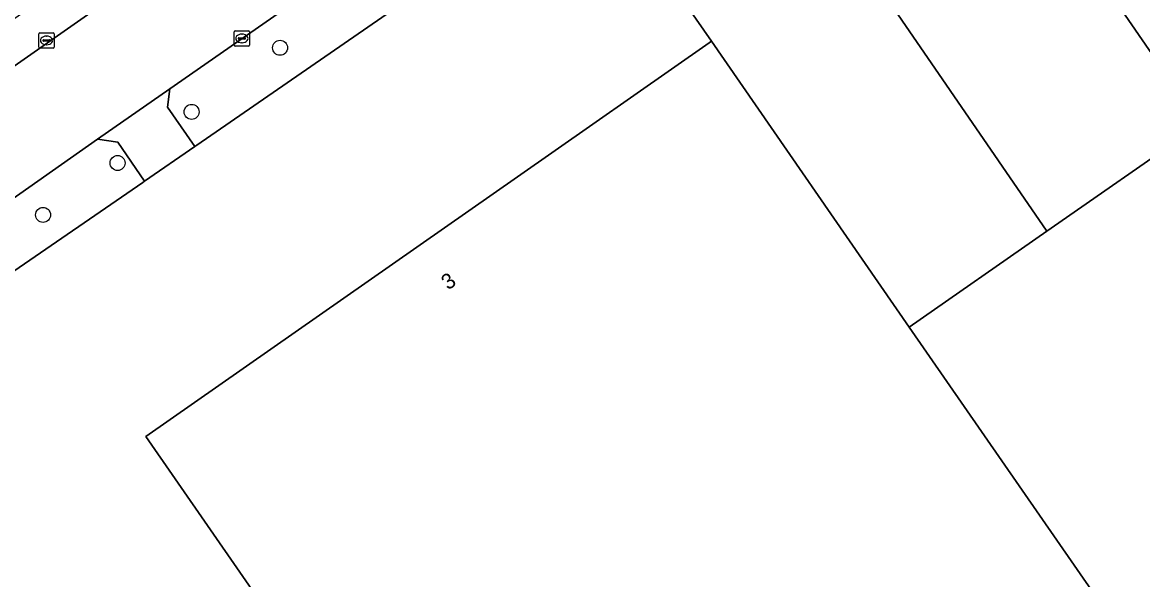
# Model space of a CAD drawing. Extents: x 156702 to 158052, y 387630 to 388992.
# Drawn here: x 157218.4 to 157291.3, y 388018.3 to 388054.6 of the extents above; entities that cross this region are included whole.
import ezdxf

# ---------------------------------------------------------------- set-up
doc = ezdxf.new("R2010")
doc.units = 0
for name, color, linetype in [('IMGEO_Berm_groen', 7, 'Continuous'), ('IMGEO_Boom', 7, 'Continuous'), ('IMGEO_Erf', 7, 'Continuous'), ('IMGEO_Kolk', 7, 'Continuous'), ('IMGEO_Pand', 7, 'Continuous'), ('IMGEO_Pand_nummerreeks', 7, 'Continuous'), ('IMGEO_Parkeervlak_open', 7, 'Continuous'), ('IMGEO_Rijbaan_lokaal_gesloten', 7, 'Continuous'), ('IMGEO_Voetpad_open', 7, 'Continuous')]:
    doc.layers.add(name, color=color, linetype=linetype)

msp = doc.modelspace()

# ---------------------------------------------------------------- linework, layer by layer
at = {"layer": 'IMGEO_Berm_groen'}
for points in [[(157243.07, 388055.771), (157240.821, 388059.195), (157228.017, 388050.255), (157227.867, 388049.069), (157229.656, 388046.52), (157229.78, 388046.605)], [(157226.257, 388044.175), (157226.369, 388044.252), (157224.647, 388046.795), (157223.322, 388046.977), (157216.483, 388042.202), (157217.546, 388040.691), (157216.399, 388039.902), (157217.532, 388038.158)]]:
    msp.add_lwpolyline(points, close=True, dxfattribs=at)
at = {"layer": 'IMGEO_Boom'}
for centre in [(157235.188, 388052.93), (157229.437, 388048.762), (157224.623, 388045.438), (157219.777, 388042.063)]:
    msp.add_circle(centre, 0.489, dxfattribs=at)
at = {"layer": 'IMGEO_Erf'}
for points in [[(157295.814, 388092.422), (157290.104, 388088.445), (157280.155, 388081.516), (157245.365, 388057.354), (157243.07, 388055.771), (157229.78, 388046.605), (157229.656, 388046.52), (157226.369, 388044.252), (157226.257, 388044.175), (157217.532, 388038.158), (157206.185, 388030.086), (157205.385, 388029.517), (157201.094, 388026.55), (157192.622, 388020.62), (157173.094, 388007.069), (157165.32, 388001.584), (157139.646, 387983.642), (157132.369, 387978.596), (157115.369, 387966.676)], [(157240.973, 388006.687), (157226.45, 388027.647), (157250.631, 388044.541), (157263.091, 388053.246), (157263.242, 388053.365), (157260.745, 388056.949)]]:
    msp.add_lwpolyline(points, dxfattribs=at)
at = {"layer": 'IMGEO_Kolk'}
for p, q in [((157219.503, 388052.979), (157219.503, 388053.831)), ((157219.578, 388053.905), (157220.43, 388053.905)), ((157219.991, 388053.685), (157220.016, 388053.685)), ((157220.504, 388053.831), (157220.504, 388052.979)), ((157232.204, 388053.109), (157232.204, 388053.961)), ((157232.279, 388054.035), (157233.131, 388054.035)), ((157232.463, 388053.529), (157232.463, 388053.541)), ((157232.901, 388053.492), (157232.503, 388053.492)), ((157232.506, 388053.578), (157232.904, 388053.578)), ((157232.692, 388053.815), (157232.717, 388053.815)), ((157232.947, 388053.541), (157232.947, 388053.529)), ((157233.205, 388053.961), (157233.205, 388053.109)), ((157220.43, 388052.905), (157219.578, 388052.905)), ((157219.762, 388053.399), (157219.762, 388053.411)), ((157220.2, 388053.362), (157219.802, 388053.362)), ((157219.805, 388053.448), (157220.203, 388053.448)), ((157220.014, 388053.125), (157219.989, 388053.125)), ((157220.246, 388053.411), (157220.246, 388053.399)), ((157233.131, 388053.035), (157232.279, 388053.035)), ((157232.715, 388053.255), (157232.69, 388053.255))]:
    msp.add_line(p, q, dxfattribs=at)
for points in [[(157219.503, 388052.979), (157219.503, 388053.831)], [(157219.578, 388053.905), (157220.43, 388053.905)], [(157220.504, 388053.831), (157220.504, 388052.979)], [(157232.204, 388053.109), (157232.204, 388053.961)], [(157232.279, 388054.035), (157233.131, 388054.035)], [(157233.205, 388053.961), (157233.205, 388053.109)], [(157220.43, 388052.905), (157219.578, 388052.905)], [(157233.131, 388053.035), (157232.279, 388053.035)]]:
    msp.add_lwpolyline(points, dxfattribs=at)
for centre, radius, start, end in [((157219.58, 388053.829), 0.0765, 91.55205, 178.44795), ((157219.58, 388053.829), 0.0765, 91.55205, 178.44795), ((157220.428, 388053.829), 0.0765, 1.55205, 88.44795), ((157220.428, 388053.829), 0.0765, 1.55205, 88.44795), ((157232.281, 388053.959), 0.0765, 91.55205, 178.44795), ((157232.281, 388053.959), 0.0765, 91.55205, 178.44795), ((157232.503, 388053.538), 0.0403, 85.87752, 175.75265), ((157232.5, 388053.528), 0.0366, 178.93798, 274.71019), ((157232.904, 388053.535), 0.043, 264.86636, 352.45326), ((157232.908, 388053.54), 0.0386, 1.73085, 96.63898), ((157233.129, 388053.959), 0.0765, 1.55205, 88.44795), ((157233.129, 388053.959), 0.0765, 1.55205, 88.44795), ((157219.58, 388052.981), 0.0765, 181.55205, 268.44795), ((157219.58, 388052.981), 0.0765, 181.55205, 268.44795), ((157219.802, 388053.408), 0.0403, 85.87752, 175.75265), ((157219.799, 388053.398), 0.0366, 178.93798, 274.71019), ((157220.203, 388053.405), 0.043, 264.86636, 352.45326), ((157220.207, 388053.41), 0.0386, 1.73085, 96.63898), ((157220.428, 388052.981), 0.0765, 271.55205, 358.44795), ((157220.428, 388052.981), 0.0765, 271.55205, 358.44795), ((157232.281, 388053.111), 0.0765, 181.55205, 268.44795), ((157232.281, 388053.111), 0.0765, 181.55205, 268.44795), ((157233.129, 388053.111), 0.0765, 271.55205, 358.44795), ((157233.129, 388053.111), 0.0765, 271.55205, 358.44795)]:
    msp.add_arc(centre, radius, start, end, dxfattribs=at)
for centre, major_axis, ratio, start_param, end_param in [((157219.99, 388053.405), (-0.387, 0.002), 0.722429, 4.712389, 7.853982), ((157220.015, 388053.405), (-0.39, 0.002), 0.717154, 1.570796, 4.712389), ((157232.691, 388053.535), (-0.387, 0.002), 0.722429, 4.712389, 7.853982), ((157232.716, 388053.535), (-0.39, 0.002), 0.717154, 1.570796, 4.712389)]:
    msp.add_ellipse(centre, major_axis=major_axis, ratio=ratio, start_param=start_param, end_param=end_param, dxfattribs=at)
at = {"layer": 'IMGEO_Pand'}
for points in [[(157304.913, 388054.921), (157289.283, 388077.665), (157285.704, 388076.799), (157285.763, 388076.496), (157286.07, 388076.547), (157287, 388075.214), (157280.679, 388070.849), (157280.518, 388071.054), (157279.321, 388070.766), (157295.004, 388048.007)], [(157285.053, 388040.999), (157294.657, 388047.688), (157295.004, 388048.007), (157279.321, 388070.766), (157275.859, 388069.933), (157275.932, 388069.637), (157276.254, 388069.681), (157277.167, 388068.366), (157270.869, 388063.99), (157270.673, 388064.204), (157269.327, 388063.886)], [(157285.053, 388040.999), (157269.327, 388063.886), (157266.032, 388063.108), (157266.111, 388062.802), (157266.373, 388062.831), (157267.312, 388061.487), (157260.745, 388056.949), (157263.242, 388053.365), (157276.098, 388034.761)], [(157333.716, 388032.919), (157325.284, 388045.037), (157326.381, 388046.439), (157323.784, 388048.53), (157323.348, 388047.818), (157319.026, 388054.029), (157308.289, 388046.541), (157309.049, 388045.451), (157300.378, 388039.443), (157294.657, 388047.688), (157285.053, 388040.999), (157276.098, 388034.761), (157297.752, 388003.524), (157297.944, 388003.658), (157299.616, 388001.233), (157322.97, 388017.506), (157327.072, 388020.364), (157323.352, 388025.662)], [(157276.098, 388034.761), (157263.242, 388053.365), (157263.091, 388053.246), (157250.631, 388044.541), (157226.45, 388027.647), (157240.973, 388006.687), (157245.602, 388000), (157260.917, 387977.877), (157292.934, 388000), (157292.855, 388000.114), (157297.752, 388003.524)]]:
    msp.add_lwpolyline(points, close=True, dxfattribs=at)
at = {"layer": 'IMGEO_Parkeervlak_open'}
msp.add_lwpolyline([(157227.867, 388049.069), (157228.017, 388050.255), (157223.322, 388046.977), (157224.647, 388046.795), (157226.369, 388044.252), (157229.656, 388046.52)], close=True, dxfattribs=at)
at = {"layer": 'IMGEO_Rijbaan_lokaal_gesloten'}
for points in [[(157284.592, 388098.393), (157283.996, 388097.937), (157223.111, 388055.38), (157209.651, 388045.972), (157202.564, 388041.019), (157199.881, 388039.143), (157191.985, 388033.624), (157171.05, 388018.99), (157160.984, 388011.954), (157153.663, 388006.837), (157136.217, 387994.642), (157131.493, 387991.34), (157121.046, 387984.038), (157104.658, 387972.583), (157104.516, 387972.484)], [(157216.483, 388042.202), (157223.322, 388046.977), (157228.017, 388050.255), (157240.821, 388059.195), (157241.912, 388059.957), (157278.905, 388085.793), (157287.685, 388091.892), (157293.209, 388095.729)]]:
    msp.add_lwpolyline(points, dxfattribs=at)
at = {"layer": 'IMGEO_Voetpad_open'}
msp.add_lwpolyline([(157223.111, 388055.38), (157221.662, 388057.453), (157208.195, 388048.04), (157209.651, 388045.972)], close=True, dxfattribs=at)

# ---------------------------------------------------------------- texts
at = {"layer": 'IMGEO_Pand_nummerreeks'}
msp.add_text('3', height=1, rotation=34.729, dxfattribs=at).set_placement((157246.111, 388037.143))

doc.saveas('drawing.dxf')
